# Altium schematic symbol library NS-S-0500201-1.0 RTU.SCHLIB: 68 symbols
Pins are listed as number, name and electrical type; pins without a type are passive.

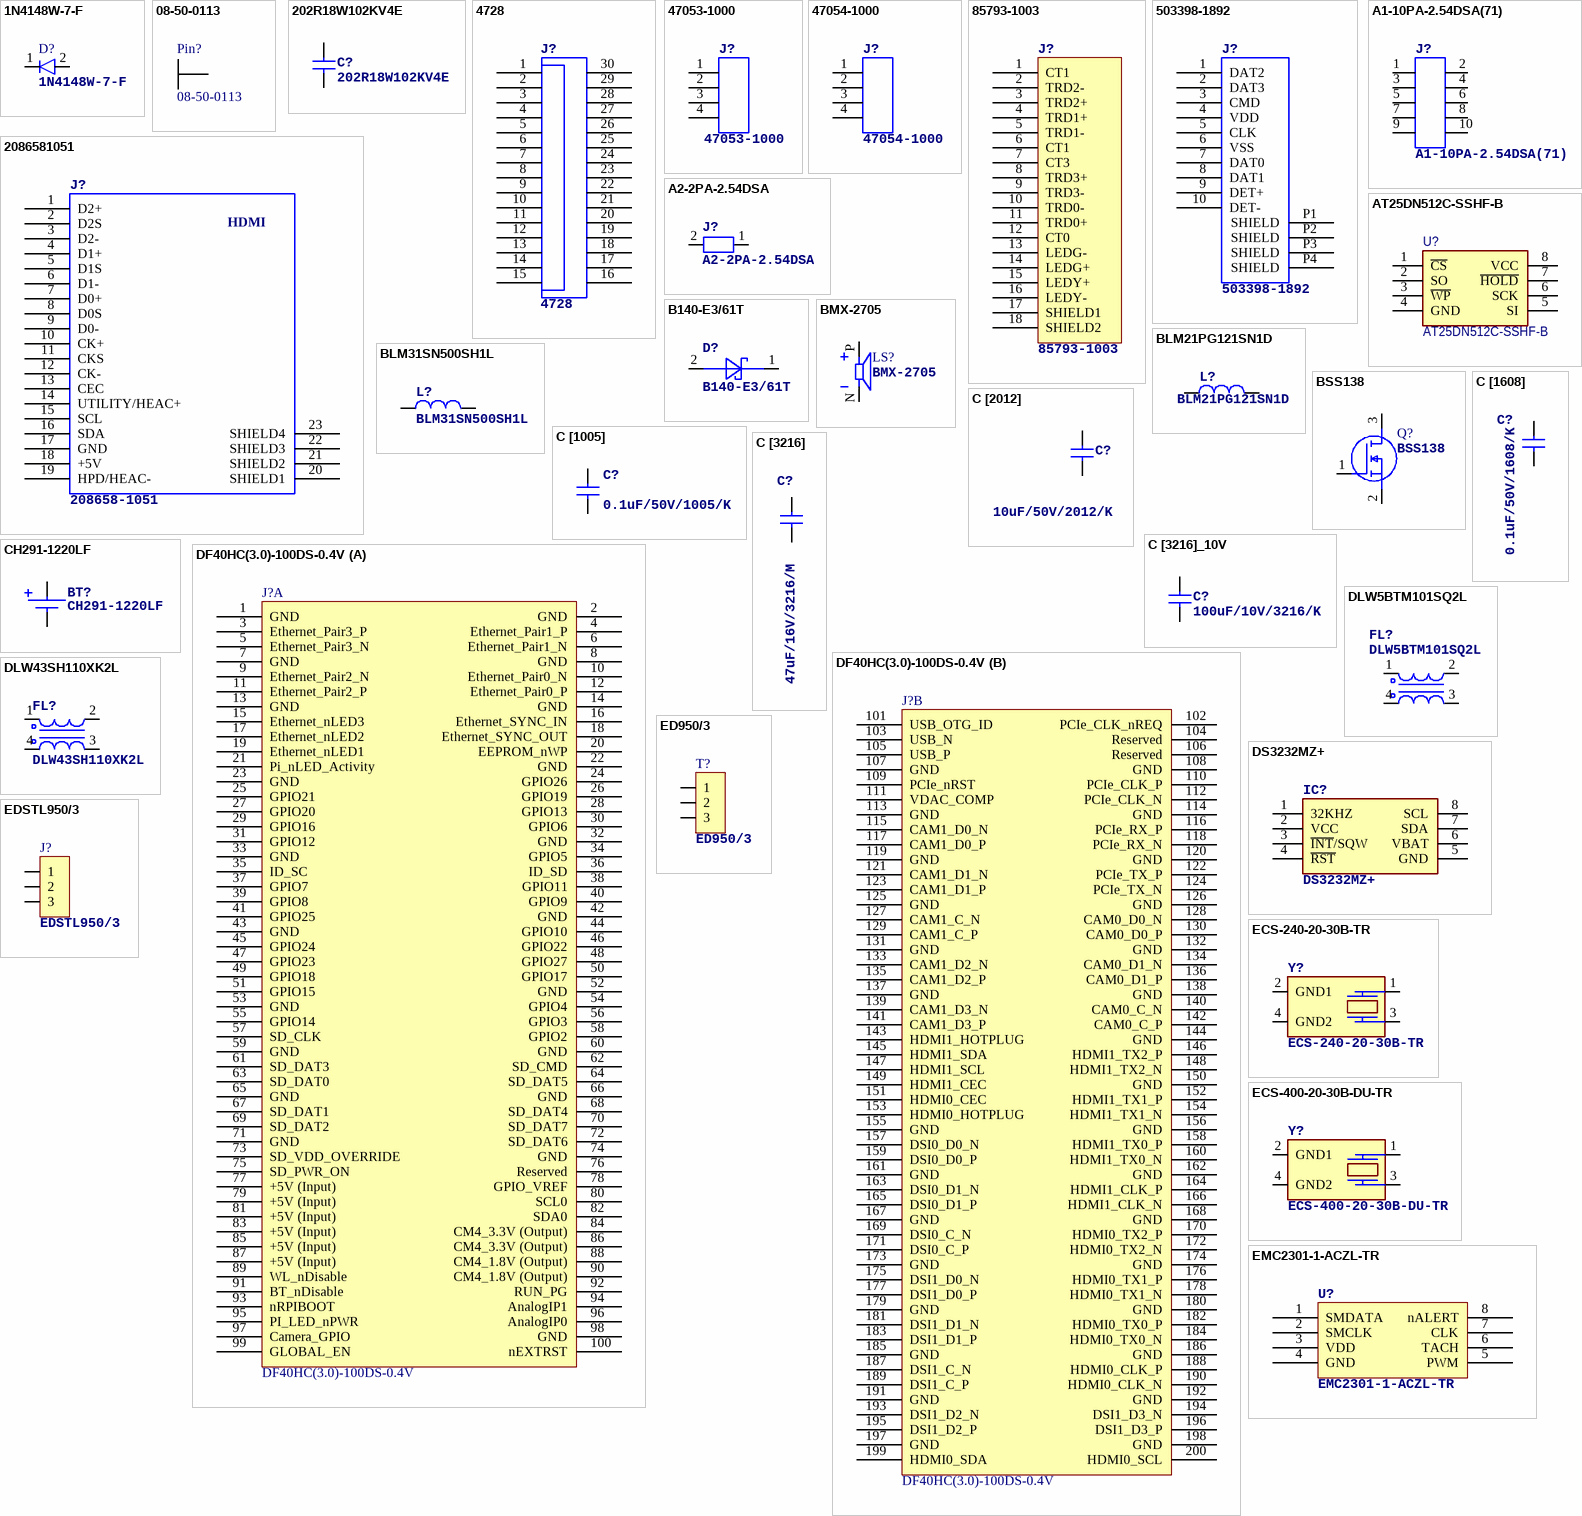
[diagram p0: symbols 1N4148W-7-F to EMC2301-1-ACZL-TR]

## 1N4148W-7-F
designator D?
Diodes - General Purpose, Power, Switching SURFACE MOUNT FAST SWITCHING DIODE; Manufacturer_Name: Diodes Inc.; Maker: Diodes Incorporated
footprint SOD-123
pins: 1, 2

## 08-50-0113
designator Pin?  (mechanical)
Headers & Wire Housings KK TERM 22-30G / (Use with 47054-1000); Maker: Molex

## 202R18W102KV4E
designator C?
Multilayer Ceramic Capacitors MLCC - SMD/SMT 2Kvolts 1000pF 10% X7R; Value: 2000V/1000pF
footprint C3216 (Chip Capacitor, 2-Leads, Body 3.2x1.6mm, IPC Medium Density)
pins: 1, 2

## 4728
designator J?
Raspberry Pi Accessories Replacement CSI/DSI Connector for Raspberry Pi - Repair Part; Maker: Adafruit
footprint 4728 (FFC_CONNECTOR)
pins: 1, 2, 3, 4, 5, 6, 7, 8, 9, 10, 11, 12, 13, 14, 15, 16, 17, 18, 19, 20, 21, 22, 23, 24, 25, 26, 27, 28, 29, 30

## 47053-1000
designator J?
KK 254 Vertical Header, with Friction Lock, 4 Circuits, PC Tail Length 3.50mm, Bag; Maker: Molex; Plating: 151ConductorMaterial; Number of Contacts: 4; Gender: Male; Current Rating: 4A; Voltage Rating: 250V; Pitch: 2.54mm; Glow Wire Compliant: Non-compliant
footprint 47053-1000
pins: 1, 2, 3, 4

## 47054-1000
designator J?  (mechanical)
Headers & Wire Housings KK .100" HSG 04P; PartNo.: 47053-1000; Maker: Molex
pins: 1, 2, 3, 4

## 85793-1003
designator J?
Gigabit Ethernet Connectors 8/8 RA Magnetic Jack Grn/Orange/Grn LED; Maker: Molex
footprint MOLEX_85793-1003
pins: 1 CT1, 2 TRD2-, 3 TRD2+, 4 TRD1+, 5 TRD1-, 6 CT1, 7 CT3, 8 TRD3+, 9 TRD3-, 10 TRD0-, 11 TRD0+, 12 CT0, 13 LEDG-, 14 LEDG+, 15 LEDY+, 16 LEDY-, 17 SHIELD1, 18 SHIELD2

## 503398-1892
designator J?
Memory Card Connectors MICRO SD PUSH/PUSH NORMAL 1.28MM 8C; Maker: Molex
footprint MOLEX_503398-1892
pins: 1 DAT2, 2 DAT3, 3 CMD, 4 VDD, 5 CLK, 6 VSS, 7 DAT0, 8 DAT1, 9 DET+, 10 DET-, P1 SHIELD, P2 SHIELD, P3 SHIELD, P4 SHIELD

## 2086581051
designator J?, comment 208658-1051
HDMI 2.1 Receptacle Connector 19 Position Surface Mount, Right Angle; Through Hole; PartNo.: 2086581051; Maker: Molex
footprint MOLEX_208658-1051
pins: 1 D2+, 2 D2S, 3 D2-, 4 D1+, 5 D1S, 6 D1-, 7 D0+, 8 D0S, 9 D0-, 10 CK+, 11 CKS, 12 CK-, 13 CEC, 14 UTILITY/HEAC+, 15 SCL, 16 SDA, 17 GND, 18 +5V, 19 HPD/HEAC-, 20 SHIELD1, 21 SHIELD2, 22 SHIELD3, 23 SHIELD4

## A1-10PA-2.54DSA(71)
designator J?
Headers & Wire Housings 10P M PIN HEADER DR STRAIGHT TYPE GOLD; Maker: Hirose
footprint A1-10PA-2.54DSA
pins: 1, 2, 3, 4, 5, 6, 7, 8, 9, 10

## A2-2PA-2.54DSA
designator J?
Headers & Wire Housings 2P M PIN HEADER SR STRAIGHT TYPE GOLD; Maker: HIROSE
footprint A2-2PA-2.54DSA
pins: 1, 2

## AT25DN512C-SSHF-B
designator U?
NOR Flash 512 Kbit, 3.0V (2.3V to 3.6V), -40C to 85C, SOIC-N 150mil (Tube), Single, Dual SPI NOR flash; Maker: Renesas / Dialog
footprint SOIC8_1.27_6.0
pins: 1 ~{CS}, 2 SO, 3 ~{WP}, 4 GND, 5 SI, 6 SCK, 7 ~{HOLD}, 8 VCC

## B140-E3/61T
designator D?
Schottky Diodes & Rectifiers 1.0 Amp 40 Volt; Maker: Vishay
footprint DO-214AC(SMA)_21
pins: 1 Cathode, 2 Anode

## BLM21PG121SN1D
designator L?
Ferrite Beads Multi-Layer 120Ohm 25% 100MHz 3A 30mOhm DCR 0805 Paper T/R; Maker: MURATA; Material: Steel,Ferrite; Impedance: 120R; DC Resistance (DCR): 30mR; Number of Lines: 1
footprint L2012 (Chip Inductor, 2-Leads, Body 2.0x1.2mm, IPC Medium Density)
pins: 1, 2

## BLM31SN500SH1L
designator L?
Ferrite Beads Multi-Layer Power 50Ohm 25% 100MHz 12A 0.0016Ohm DCR 1206 Automotive T/R; Maker: MURATA; Number of Lines: 1; DC Resistance (DCR): 1.6mR
footprint L3216 (Chip Inductor, 2-Leads, Body 3.2x1.6mm, IPC Medium Density)
pins: 1, 2

## BMX-2705
designator LS?
9 mm, 5 Vdc, 90 dB, SMD Passive, Magnetic Audio Indicator Buzzer; Maker: KANGSEO EST
footprint BUZZER-BMX-2705
pins: N, P

## BSS138
designator Q?
MOSFET (N-Channel); Manufacturer_Name: ON Semiconductor
footprint SOT23L
pins: 1 G, 2 S, 3 D

## C [1005]
designator C?  value 0.1uF/50V/1005/K  (hidden comment: C [1005])  (no BOM)
MLCC - SMD/SMT 50V X5R +/-10% 1005(mm)
footprint C1005 (Chip Capacitor, 2-Leads, Body 1.0x0.5mm, IPC Medium Density)
pins: 1, 2

## C [1608]
designator C?  value 0.1uF/50V/1608/K  (hidden comment: C [1608])
MLCC - SMD/SMT 50V X5R +/-10% 1608(mm)
footprint C1608 (Chip Capacitor, 2-Leads, Body 1.6x0.8mm, IPC Medium Density)
pins: 1, 2

## C [2012]
designator C?  value 10uF/50V/2012/K  (hidden comment: C [2012])
MLCC - SMD/SMT 50V X5R +/-10% 2012(mm)
footprint C2012 (Chip Capacitor, 2-Leads, Body 2.0x1.2mm, IPC Medium Density)
footprint C2012 (Chip Capacitor, 2-Leads, Body 2.0x1.2mm, IPC Medium Density)
pins: 1, 2

## C [3216]
designator C?  value 47uF/16V/3216/M  (hidden comment: C [3216])
MLCC - SMD/SMT 50V X5R +/-10% 3216(mm)
footprint C3216 (Chip Capacitor, 2-Leads, Body 3.2x1.6mm, IPC Medium Density)
pins: 1, 2

## C [3216]_10V
designator C?, comment value 100uF/10V/3216/K  (hidden comment: C [3216])
MLCC - SMD/SMT 10V X5R +/-10% 3216(mm)
footprint C3216 (Chip Capacitor, 2-Leads, Body 3.2x1.6mm, IPC Medium Density)
pins: 1, 2

## CH291-1220LF
designator BT?
Battery Holder (CR1220 Need); Maker: Multicomp
footprint CH291-1220LF
pins: 1, 2

## DF40HC(3.0)-100DS-0.4V
designator J?
Board to Board & Mezzanine Connectors 100P 2R 3MM RECPT SMT VERT 0.4MM PITCH; Maker: Hirose
footprint DF40HC(3.0)-100DS-0.4V
part A pins: 1 GND, 2 GND, 3 Ethernet_Pair3_P, 4 Ethernet_Pair1_P, 5 Ethernet_Pair3_N, 6 Ethernet_Pair1_N, 7 GND, 8 GND, 9 Ethernet_Pair2_N, 10 Ethernet_Pair0_N, 11 Ethernet_Pair2_P, 12 Ethernet_Pair0_P, 13 GND, 14 GND, 15 Ethernet_nLED3, 16 Ethernet_SYNC_IN, 17 Ethernet_nLED2, 18 Ethernet_SYNC_OUT, 19 Ethernet_nLED1, 20 EEPROM_nWP, 21 Pi_nLED_Activity, 22 GND, 23 GND, 24 GPIO26, 25 GPIO21, 26 GPIO19, 27 GPIO20, 28 GPIO13, 29 GPIO16, 30 GPIO6, 31 GPIO12, 32 GND, 33 GND, 34 GPIO5, 35 ID_SC, 36 ID_SD, 37 GPIO7, 38 GPIO11, 39 GPIO8, 40 GPIO9, 41 GPIO25, 42 GND, 43 GND, 44 GPIO10, 45 GPIO24, 46 GPIO22, 47 GPIO23, 48 GPIO27, 49 GPIO18, 50 GPIO17, 51 GPIO15, 52 GND, 53 GND, 54 GPIO4, 55 GPIO14, 56 GPIO3, 57 SD_CLK, 58 GPIO2, 59 GND, 60 GND, 61 SD_DAT3, 62 SD_CMD, 63 SD_DAT0, 64 SD_DAT5, 65 GND, 66 GND, 67 SD_DAT1, 68 SD_DAT4, 69 SD_DAT2, 70 SD_DAT7, 71 GND, 72 SD_DAT6, 73 SD_VDD_OVERRIDE, 74 GND, 75 SD_PWR_ON, 76 Reserved, 77 +5V (Input), 78 GPIO_VREF, 79 +5V (Input), 80 SCL0, 81 +5V (Input), 82 SDA0, 83 +5V (Input), 84 CM4_3.3V (Output), 85 +5V (Input), 86 CM4_3.3V (Output), 87 +5V (Input), 88 CM4_1.8V (Output), 89 WL_nDisable, 90 CM4_1.8V (Output), 91 BT_nDisable, 92 RUN_PG, 93 nRPIBOOT, 94 AnalogIP1, 95 PI_LED_nPWR, 96 AnalogIP0, 97 Camera_GPIO, 98 GND, 99 GLOBAL_EN, 100 nEXTRST
part B pins: 101 USB_OTG_ID, 102 PCIe_CLK_nREQ, 103 USB_N, 104 Reserved, 105 USB_P, 106 Reserved, 107 GND, 108 GND, 109 PCIe_nRST, 110 PCIe_CLK_P, 111 VDAC_COMP, 112 PCIe_CLK_N, 113 GND, 114 GND, 115 CAM1_D0_N, 116 PCIe_RX_P, 117 CAM1_D0_P, 118 PCIe_RX_N, 119 GND, 120 GND, 121 CAM1_D1_N, 122 PCIe_TX_P, 123 CAM1_D1_P, 124 PCIe_TX_N, 125 GND, 126 GND, 127 CAM1_C_N, 128 CAM0_D0_N, 129 CAM1_C_P, 130 CAM0_D0_P, 131 GND, 132 GND, 133 CAM1_D2_N, 134 CAM0_D1_N, 135 CAM1_D2_P, 136 CAM0_D1_P, 137 GND, 138 GND, 139 CAM1_D3_N, 140 CAM0_C_N, 141 CAM1_D3_P, 142 CAM0_C_P, 143 HDMI1_HOTPLUG, 144 GND, 145 HDMI1_SDA, 146 HDMI1_TX2_P, 147 HDMI1_SCL, 148 HDMI1_TX2_N, 149 HDMI1_CEC, 150 GND, 151 HDMI0_CEC, 152 HDMI1_TX1_P, 153 HDMI0_HOTPLUG, 154 HDMI1_TX1_N, 155 GND, 156 GND, 157 DSI0_D0_N, 158 HDMI1_TX0_P, 159 DSI0_D0_P, 160 HDMI1_TX0_N, 161 GND, 162 GND, 163 DSI0_D1_N, 164 HDMI1_CLK_P, 165 DSI0_D1_P, 166 HDMI1_CLK_N, 167 GND, 168 GND, 169 DSI0_C_N, 170 HDMI0_TX2_P, 171 DSI0_C_P, 172 HDMI0_TX2_N, 173 GND, 174 GND, 175 DSI1_D0_N, 176 HDMI0_TX1_P, 177 DSI1_D0_P, 178 HDMI0_TX1_N, 179 GND, 180 GND, 181 DSI1_D1_N, 182 HDMI0_TX0_P, 183 DSI1_D1_P, 184 HDMI0_TX0_N, 185 GND, 186 GND, 187 DSI1_C_N, 188 HDMI0_CLK_P, 189 DSI1_C_P, 190 HDMI0_CLK_N, 191 GND, 192 GND, 193 DSI1_D2_N, 194 DSI1_D3_N, 195 DSI1_D2_P, 196 DSI1_D3_P, 197 GND, 198 GND, 199 HDMI0_SDA, 200 HDMI0_SCL

## DLW5BTM101SQ2L
designator FL?
Ind Common Mode Choke Wirewound 100 Ohm 100MHz 6A 2020 Embossed T/R; Manufacturer_Name: Murata Electronics; Manufacturer: Murata; Number of Lines: 2; DC Resistance (DCR): 13mR; Voltage Rating (DC): 50V; Shielding: Unshielded; Impedance: 100R; Tolerance: 40%
footprint DLW5BTM101SQ2L
pins: 1, 2, 3, 4

## DLW43SH110XK2L
designator FL?
CMC 11UH 360MA 2LN SMD AEC-Q200; Manufacturer_Name: Murata Electronics; Manufacturer: Murata; Number of Lines: 2; Tolerance: 50%; Shielding: Unshielded; DC Resistance (DCR): 500mR; Test Frequency: 100MHz
footprint DLW43SH110XK2L
pins: 1, 2, 3, 4

## DS3232MZ+
designator IC?
DS3232M Series 4.5 V ±5 ppm Surface Mount I2C Real-Time Clock - SOIC-8; Manufacturer_Name: Maxim Integrated; Manufacturer: Maxim; Memory Size: 236B; Time Format: HH:MM:SS (12/24 hr); Max Supply Voltage: 4.5V; Min Supply Voltage: 2.3V; Interface: I2C,Serial,2-Wire; Date Format: YY-MM-DD-dd
footprint SOIC8_1.27_6.0
pins: 1 32KHZ, 2 VCC, 3 ~{INT}/SQW, 4 ~{RST}, 5 GND, 6 VBAT, 7 SDA, 8 SCL

## ECS-240-20-30B-TR
designator Y?
Crystal 24MHz ±30ppm (Tol) ±50ppm (Stability) 20pF FUND 80Ohm 4-Pin Mini-SMD T/R; Maker: ECS
footprint ECS-240-20-30B-TR
pins: 1 IN/OUT, 2 GND1, 3 OUT/IN, 4 GND2

## ECS-400-20-30B-DU-TR
designator Y?
Crystal 40MHz ±30ppm (Tol) ±100ppm (Stability) 20pF FUND 100Ohm 4-Pin Mini-SMD T/R; Maker: ECS
footprint ECS-400-20-30B-DU-TR
pins: 1 IN/OUT, 2 GND1, 3 OUT/IN, 4 GND2

## ED950/3
designator T?  (mechanical)
TERM BLOCK PLUG 3POS STR 5MM; Maker: OnShore
pins: 1, 2, 3
2 alternate drawings of the same symbol

## EDSTL950/3
designator J?
Connector
footprint EDSTL950_3
pins: 1, 2, 3
2 alternate drawings of the same symbol

## EMC2301-1-ACZL-TR
designator U?
Board Mount Temperature Sensors Single RPB-Based PWM Fan Speed CNTRL; Maker: Microchip
footprint MSOP8_0.65_5.0
pins: 1 SMDATA, 2 SMCLK, 3 VDD, 4 GND, 5 PWM, 6 TACH, 7 CLK, 8 nALERT

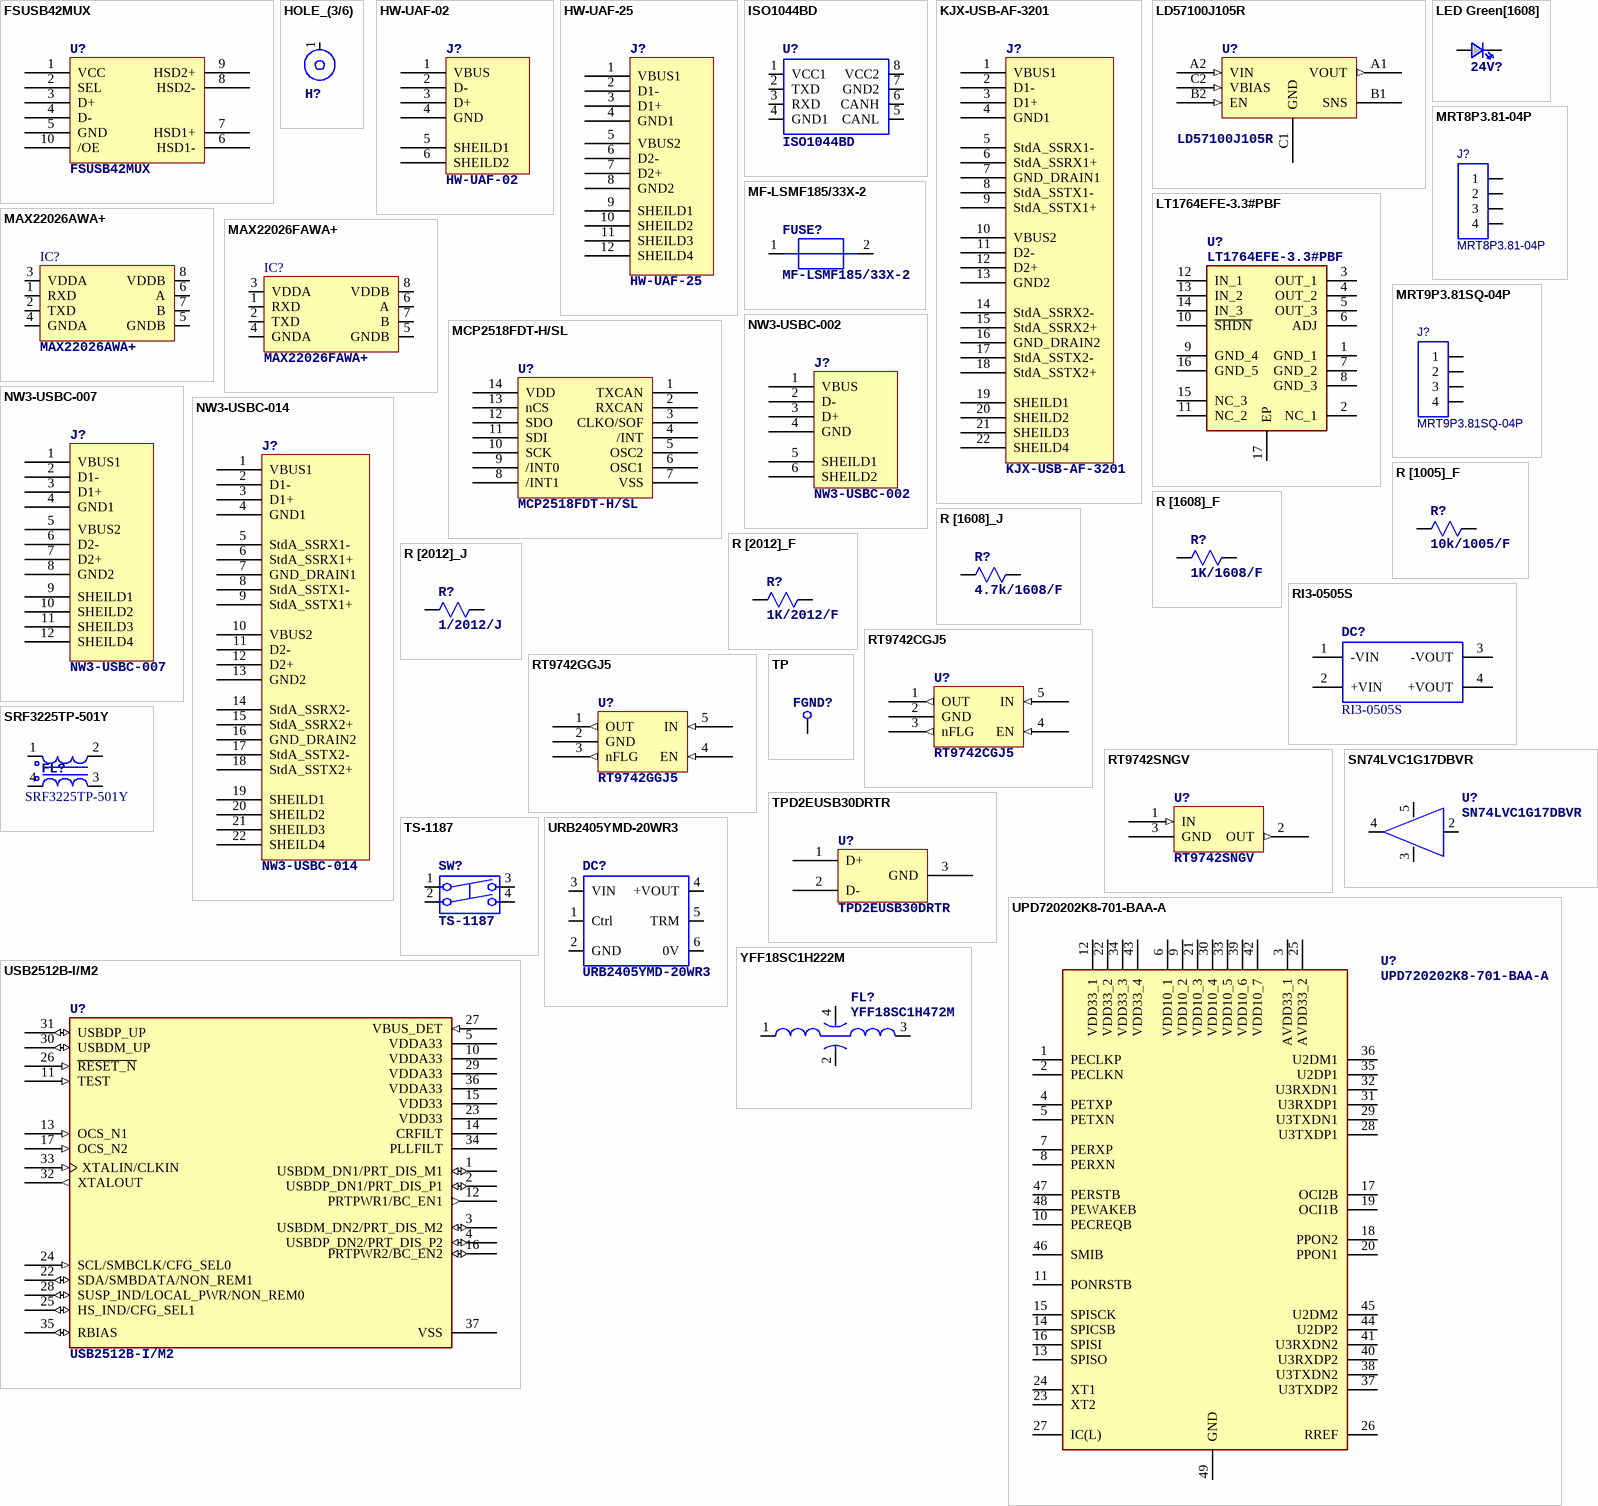
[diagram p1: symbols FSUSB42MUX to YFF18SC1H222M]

## FSUSB42MUX
designator U?
USB Switch ICs Low Power, Two-Port USB 2.0 (480Mbps); Maker: ONSEMI
footprint MSOP10_0.5_5.0
pins: 1 VCC, 2 SEL, 3 D+, 4 D-, 5 GND, 6 HSD1-, 7 HSD1+, 8 HSD2-, 9 HSD2+, 10 /OE

## HOLE_(3/6)
designator H?  (value not drawn)
HOLE
footprint NTH_3.6
pins: 1

## HW-UAF-02
designator J?
USB 2.0 A/F Connector, Right angle
pins: 1 VBUS, 2 D-, 3 D+, 4 GND, 5 SHEILD1, 6 SHEILD2

## HW-UAF-25
designator J?
USB 2.0 A/F 2 stack Connector, Right angle
pins: 1 VBUS1, 2 D1-, 3 D1+, 4 GND1, 5 VBUS2, 6 D2-, 7 D2+, 8 GND2, 9 SHEILD1, 10 SHEILD2, 11 SHEILD3, 12 SHEILD4

## ISO1044BD
designator U?
CAN Interface IC Isolated CAN FD transceiver in small package 8-SOIC -40 to 125; Maker: Texas Instruments
footprint SOIC8_1.27_6.0
pins: 1 VCC1, 2 TXD, 3 RXD, 4 GND1, 5 CANL, 6 CANH, 7 GND2, 8 VCC2

## KJX-USB-AF-3201
designator J?
USB 3.0 A/F 2 stack Connector, Right angle
pins: 1 VBUS1, 2 D1-, 3 D1+, 4 GND1, 5 StdA_SSRX1-, 6 StdA_SSRX1+, 7 GND_DRAIN1, 8 StdA_SSTX1-, 9 StdA_SSTX1+, 10 VBUS2, 11 D2-, 12 D2+, 13 GND2, 14 StdA_SSRX2-, 15 StdA_SSRX2+, 16 GND_DRAIN2, 17 StdA_SSTX2-, 18 StdA_SSTX2+, 19 SHEILD1, 20 SHEILD2, 21 SHEILD3, 22 SHEILD4

## LD57100J105R
designator U?
LDO Voltage Regulators 3V~5.5V to 1.05V 1A ultra low-dropout LDO bias; Maker: STMicroelectronics
footprint WLCSP6_0.4P
pins: A1 VOUT (out), A2 VIN (in), B1 SNS, B2 EN (in), C1 GND, C2 VBIAS (in)

## LED Green[1608]
designator 24V?  (value not drawn)
Standard LEDs - SMD SMD 1608(mm) GREEN
footprint LED1608
pins: 1 A, 2 K

## LT1764EFE-3.3#PBF
designator U?
LDO Regulator Pos 3.3V 3A 16-Pin TSSOP EP; Manufacturer_Name: Analog Devices; Manufacturer: Analog Devices / Linear Technology; Dropout Voltage: 340mV; Number of Regulators: 1; Min Current Limit: 3.1A; Value: 3.3V/3A
footprint TSSOP16-0.65_6.5_EP
pins: 1 GND_1, 2 NC_1, 3 OUT_1, 4 OUT_2, 5 OUT_3, 6 ADJ, 7 GND_2, 8 GND_3, 9 GND_4, 10 ~{SHDN}, 11 NC_2, 12 IN_1, 13 IN_2, 14 IN_3, 15 NC_3, 16 GND_5, 17 EP

## MAX22026AWA+
designator IC?
RS422/RS485 Transceiver, -40 to 85DEG C Rohs Compliant: Yes; Manufacturer: Maxim
footprint SOIC8-1.27_7.9
pins: 1 RXD, 2 TXD, 3 VDDA, 4 GNDA, 5 GNDB, 6 A, 7 B, 8 VDDB

## MAX22026FAWA+
designator IC?
RS422/RS485 Transceiver, -40 to 85DEG C Rohs Compliant: Yes; Manufacturer: Maxim; PartNo.: MAX22026AWA+
footprint SOIC8-1.27_7.9
pins: 1 RXD, 2 TXD, 3 VDDA, 4 GNDA, 5 GNDB, 6 A, 7 B, 8 VDDB

## MCP2518FDT-H/SL
designator U?
CAN Interface IC Stand-alone Low Power CAN FD Controller s/SPI Interface Grade 0; Maker: MIcrochip
footprint SOIC14_1.27_6.0
pins: 1 TXCAN, 2 RXCAN, 3 CLKO/SOF, 4 /INT, 5 OSC2, 6 OSC1, 7 VSS, 8 /INT1, 9 /INT0, 10 SCK, 11 SDI, 12 SDO, 13 nCS, 14 VDD

## MF-LSMF185/33X-2
designator FUSE?
Resettable Fuses - PPTC PTC RESETTABLE 1.85A 33V SMD 2920; Maker: Bourns
footprint MF-LSMF185_33X-2
pins: 1, 2

## MRT8P3.81-04P
designator J?  (mechanical)
TERM BLOCK PLUG 4POS STR 3.81mm(MRT9P3.81SQ-04P need); Maker: STELVIO
pins: 1, 2, 3, 4

## MRT9P3.81SQ-04P
designator J?
Through Hole 4p right angle DIP (MRT8P3.81-04P need); Maker: STELVIO
footprint MRT9P3.81SQ-04P
pins: 1, 2, 3, 4

## NW3-USBC-002
designator J?
USB 2.0 A/F Connector, Right angle; Maker: NW3
footprint NW3-USBC-002
pins: 1 VBUS, 2 D-, 3 D+, 4 GND, 5 SHEILD1, 6 SHEILD2

## NW3-USBC-007
designator J?
USB 2.0 A/F 2 stack Connector, Right angle; Maker: NW3
footprint NW3-USBC-007
pins: 1 VBUS1, 2 D1-, 3 D1+, 4 GND1, 5 VBUS2, 6 D2-, 7 D2+, 8 GND2, 9 SHEILD1, 10 SHEILD2, 11 SHEILD3, 12 SHEILD4

## NW3-USBC-014
designator J?
USB 3.0 A/F 2 stack Connector, Right angle; Maker: NW3
footprint NW3-USBC-014
pins: 1 VBUS1, 2 D1-, 3 D1+, 4 GND1, 5 StdA_SSRX1-, 6 StdA_SSRX1+, 7 GND_DRAIN1, 8 StdA_SSTX1-, 9 StdA_SSTX1+, 10 VBUS2, 11 D2-, 12 D2+, 13 GND2, 14 StdA_SSRX2-, 15 StdA_SSRX2+, 16 GND_DRAIN2, 17 StdA_SSTX2-, 18 StdA_SSTX2+, 19 SHEILD1, 20 SHEILD2, 21 SHEILD3, 22 SHEILD4

## R [1005]_F
designator R?  value 10k/1005/F  (hidden comment: R [1005]_F)
SMD  Chip Resistor +/-1% 1005(mm)
footprint R1005 (Chip Resistor, 2-Leads, Body 1.00x0.50mm, IPC Medium Density)
pins: 1, 2

## R [1608]_F
designator R?  value 1K/1608/F  (hidden comment: R [1608]_F)
SMD  Chip Resistor +/-1% 1608(mm)
footprint R1608 (Chip Resistor, 2-Leads, Body 1.60x0.80mm, IPC Medium Density)
pins: 1, 2

## R [1608]_J
designator R?  value 4.7k/1608/F  (hidden comment: R [1608]_J)
SMD  Chip Resistor +/-5% 1608(mm)
footprint R1608 (Chip Resistor, 2-Leads, Body 1.60x0.80mm, IPC Medium Density)
pins: 1, 2

## R [2012]_F
designator R?  value 1K/2012/F  (hidden comment: R [2012]_F)
SMD  Chip Resistor +/-1% 2012(mm)
footprint R2012 (Chip Resistor, 2-Leads, Body 2.00x1.20mm, IPC Medium Density)
pins: 1, 2

## R [2012]_J
designator R?  value 1/2012/J  (hidden comment: R [2012]_J)
SMD  Chip Resistor +/-5% 2012(mm)
footprint R2012 (Chip Resistor, 2-Leads, Body 2.00x1.20mm, IPC Medium Density)
pins: 1, 2

## RI3-0505S
designator DC?
Isolated Module DC DC Converter 1 Output 5V 600mA 4.5V - 5.5V Input; Maker: RECOM Power
footprint RI3-0505S
pins: 1 -VIN (power), 2 +VIN (power), 3 -VOUT (power), 4 +VOUT (power)

## RT9742CGJ5
designator U?
Power Switch ICs - Power Distribution 70mohm, 2A High-Side Power Switches with flag; Maker: Richtek
footprint SOT23_5
pins: 1 OUT (out), 2 GND, 3 nFLG (out), 4 EN (in), 5 IN (in)

## RT9742GGJ5
designator U?
Power Switch ICs - Power Distribution 70mohm, 1A High-Side Power Switches with flag; Maker: Richtek
footprint SOT23_5
pins: 1 OUT (out), 2 GND, 3 nFLG (out), 4 EN (in), 5 IN (in)

## RT9742SNGV
designator U?
Power Switch ICs - Power Distribution 70mohm, 0.5A High-Side Power Switches, Current Limiter; Maker: Richtek
footprint SOT23L
pins: 1 IN (in), 2 OUT (out), 3 GND

## SN74LVC1G17DBVR
designator U?
Buffers & Line Drivers Single Schmitt-Trgr; Maker: TI
footprint SOT23_5
pins: 1 hidden, 2 A, 3, 4 Y, 5

## SRF3225TP-501Y
designator FL?
CMC,filter , 3.2x2.5x2.2mm,500ohm+/-25%,2A,shd
pins: 1, 2, 3, 4

## TP
designator FGND?  (value not drawn)
TEST POINT 1PI; PartNo.: ST-1-1
footprint ST-1-1
pins: 1

## TPD2EUSB30DRTR
designator U?
ESD Suppressors / TVS Diodes 2Ch ESD Solution; PartNo.: Package; Maker: TI
footprint SOT23L
pins: 1 D+, 2 D-, 3 GND

## TS-1187
designator SW?
SMD type SWITCH; Maker: SY Hitech
footprint TS-1187
pins: 1, 2, 3, 4

## UPD720202K8-701-BAA-A
designator U?
PD720202 is a USB host controller LSI compatible with the USB 3.0 and xHCI (eXtensible Host Controller Interface) 1.0 specifications. The system bus is compatible with the PCIe Gen2 specification. The controller provides two USB ports with LS (Low-Speed) / FS (Full-Speed) / HS (High-Speed) / SS (SuperSpeed) support.PD720202 comes in a 48-pin QFN package and has the following improvements over previous products.	Reduced power consumption in low-power mode to 4.5mW, a reduction of 90% compared with Renesas; Manufacturer_Name: Renesas Electronics; Geometry.Height: 0.9mm
footprint QFN48_0.5_7X7_EP
pins: 1 PECLKP, 2 PECLKN, 3 AVDD33_1, 4 PETXP, 5 PETXN, 6 VDD10_1, 7 PERXP, 8 PERXN, 9 VDD10_2, 10 PECREQB, 11 PONRSTB, 12 VDD33_1, 13 SPISO, 14 SPICSB, 15 SPISCK, 16 SPISI, 17 OCI2B, 18 PPON2, 19 OCI1B, 20 PPON1, 21 VDD10_3, 22 VDD33_2, 23 XT2, 24 XT1, 25 AVDD33_2, 26 RREF, 27 IC(L), 28 U3TXDP1, 29 U3TXDN1, 30 VDD10_4, 31 U3RXDP1, 32 U3RXDN1, 33 VDD10_5, 34 VDD33_3, 35 U2DP1, 36 U2DM1, 37 U3TXDP2, 38 U3TXDN2, 39 VDD10_6, 40 U3RXDP2, 41 U3RXDN2, 42 VDD10_7, 43 VDD33_4, 44 U2DP2, 45 U2DM2, 46 SMIB, 47 PERSTB, 48 PEWAKEB, 49 GND

## URB2405YMD-20WR3
designator DC?
20W isolated DC-DC converter DIP package, Ultra-wide input and regulated single output; Maker: MORNSUN
footprint URB2405YMD-20WR3
pins: 1 Ctrl, 2 GND, 3 VIN, 4 +VOUT, 5 TRM, 6 0V

## USB2512B-I/M2
designator U?
USB Interface IC 2-Port USB 2.0 Hi-Speed Hub Cont; Maker: Microchip
footprint QFN36_0.5_6X6_EP
pins: 1 USBDM_DN1/PRT_DIS_M1 (io), 2 USBDP_DN1/PRT_DIS_P1 (io), 3 USBDM_DN2/PRT_DIS_M2 (io), 4 USBDP_DN2/PRT_DIS_P2 (io), 5 VDDA33 (power), 10 VDDA33 (power), 11 TEST (in), 12 PRTPWR1/BC_EN1 (out), 13 OCS_N1 (in), 14 CRFILT (power), 15 VDD33 (power), 16 PRTPWR2/BC_EN2 (io), 17 OCS_N2 (in), 22 SDA/SMBDATA/NON_REM1 (io), 23 VDD33 (power), 24 SCL/SMBCLK/CFG_SEL0 (in), 25 HS_IND/CFG_SEL1 (io), 26 ~{RESET_N} (in), 27 VBUS_DET (in), 28 SUSP_IND/LOCAL_PWR/NON_REM0 (io), 29 VDDA33 (power), 30 USBDM_UP (io), 31 USBDP_UP (io), 32 XTALOUT (out), 33 XTALIN/CLKIN (in), 34 PLLFILT (power), 35 RBIAS (io), 36 VDDA33 (power), 37 VSS (power)

## YFF18SC1H222M
designator FL?, comment YFF18SC1H472M
Eia Case Size: 0603, Voltage: 50, Cap Value: 472, Tol: +/-20%, Thickness: 0.60 ± 0.10; Manufacturer_Name: TDK; Manufacturer_Part_Number: YFF18SC1H222MT0H0N; Capacitance: 4.7nF; Voltage Rating: 50V; Current: 1A; DC Resistance (DCR): 300mR; Insertion Loss: 30dB; Tolerance: 20%; Value: 4700pF
footprint YFF18SC1H472M
pins: 1 IN/OUT, 2 GND_1, 3 OUT/IN, 4 GND_2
